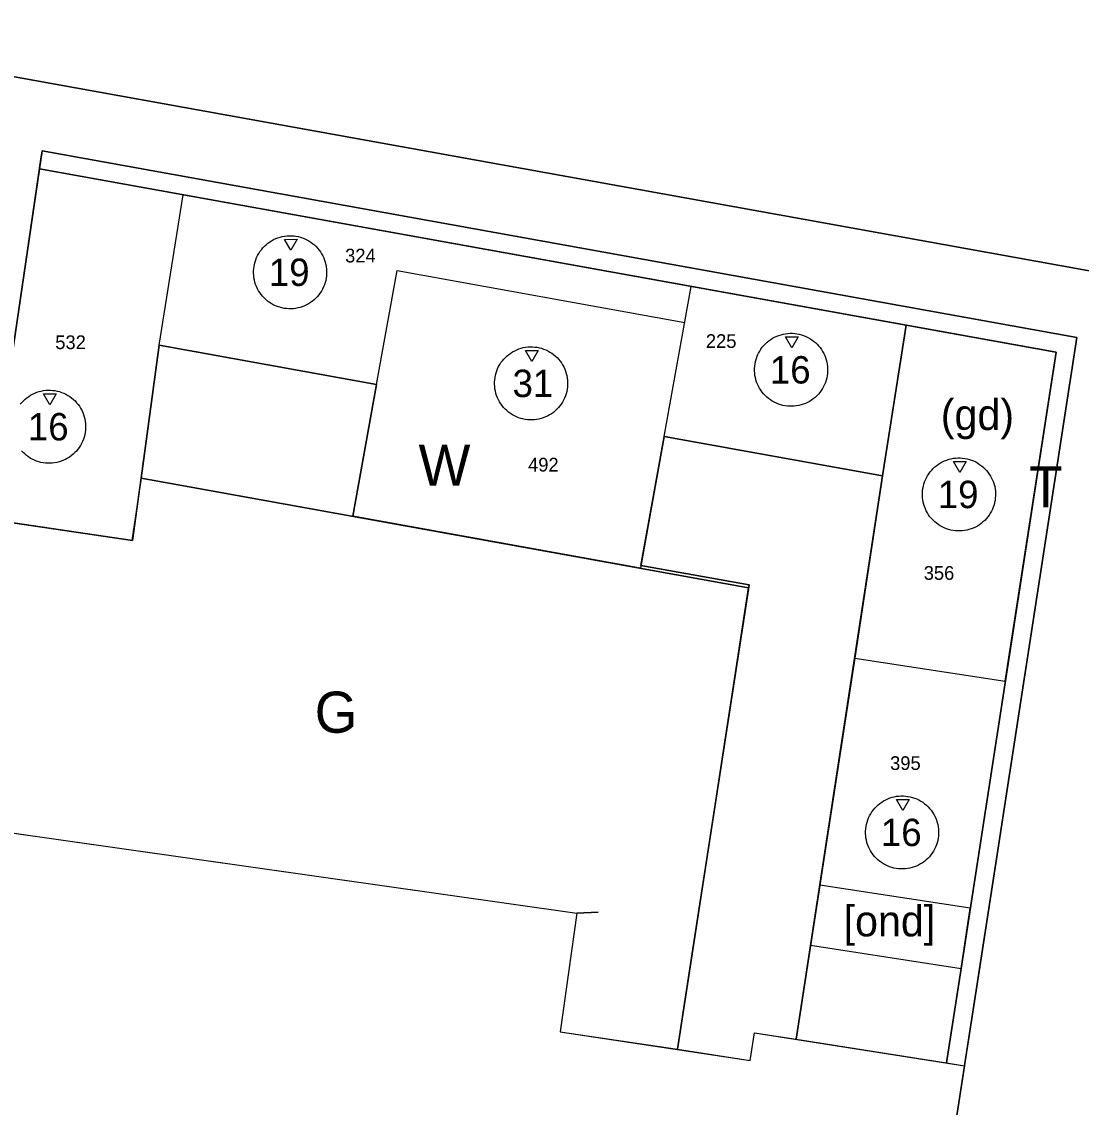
# Model space of a CAD drawing. Extents: x 104705 to 105186, y 424858 to 425816.
# Drawn here: x 104905.1 to 104992.1, y 424996.8 to 425086 of the extents above; entities that cross this region are included whole.
import ezdxf

# ---------------------------------------------------------------- set-up
doc = ezdxf.new("R2010")
doc.units = 0
for name, color, linetype in [('BP_ALG_bestemminggrens', 7, 'Continuous'), ('BP_BA_onderdoorgang', 7, 'Continuous'), ('BP_BPG_Plangebied', 7, 'Continuous'), ('BP_BV_Bouwvlak', 7, 'Continuous'), ('BP_DB_Waarde - Archeologie - 3', 7, 'Continuous'), ('BP_EB_Groen', 7, 'Continuous'), ('BP_EB_Tuin', 7, 'Continuous'), ('BP_EB_Verkeer', 7, 'Continuous'), ('BP_EB_Wonen', 7, 'Continuous'), ('BP_FA_gemengd', 7, 'Continuous'), ('BP_MV_maatvoering', 7, 'Continuous'), ('BP_TXT_tekst', 7, 'Continuous'), ('Default', 7, 'Continuous')]:
    doc.layers.add(name, color=color, linetype=linetype)

msp = doc.modelspace()

# ---------------------------------------------------------------- linework, layer by layer
at = {"layer": 'BP_ALG_bestemminggrens'}
for p, q in [((104904.141, 425057.488), (104906.778, 425075.366)), ((104991.727, 425060.043), (104906.778, 425075.366)), ((104906.559, 425073.882), (104990.022, 425058.827)), ((104984.386, 425012.461), (104991.727, 425060.043)), ((104990.022, 425058.827), (104982.903, 425012.689)), ((104914.903, 425048.497), (104964.78, 425039.501)), ((104982.903, 425012.689), (104982.217, 425008.242)), ((104983.7, 425008.013), (104984.386, 425012.461)), ((104982.217, 425008.242), (104981.021, 425000.489))]:
    msp.add_line(p, q, dxfattribs=at)
for points in [[(104894.145, 425020.819), (104895.344, 425028.689), (104897.865, 425045.778), (104914.194, 425043.37), (104914.903, 425048.497)], [(104964.78, 425039.501), (104958.936, 425001.623)], [(104977.634, 424968.696), (104983.7, 425008.013)]]:
    msp.add_lwpolyline(points, dxfattribs=at)
at = {"layer": 'BP_BA_onderdoorgang'}
msp.add_lwpolyline([(104969.863, 425010.148), (104982.217, 425008.242), (104982.98, 425013.183), (104970.626, 425015.089)], close=True, dxfattribs=at)
at = {"layer": 'BP_BPG_Plangebied'}
for points in [[(104878.613, 425085.968), (104884.922, 425084.964), (104929.095, 425077.019), (104992.295, 425065.592), (105021.483, 425060.269), (105072.728, 425051.043), (105083.131, 425049.138)], [(104884.082, 425017.207), (104884.802, 425022.147), (104950.686, 425012.785), (104949.318, 425003.038)], [(104949.318, 425003.038), (104964.917, 425000.694), (104965.27, 425002.967), (104981.021, 425000.489), (104982.501, 425000.245), (104977.634, 424968.696)]]:
    msp.add_lwpolyline(points, dxfattribs=at)
at = {"layer": 'BP_BV_Bouwvlak'}
for p, q in [((104904.141, 425057.488), (104906.559, 425073.882)), ((104906.559, 425073.882), (104989.997, 425058.831)), ((104916.372, 425059.41), (104914.194, 425043.37)), ((104934.236, 425056.188), (104916.372, 425059.41)), ((104990.022, 425058.827), (104981.021, 425000.489)), ((104932.283, 425045.362), (104934.236, 425056.188)), ((104957.855, 425051.927), (104955.902, 425041.102)), ((104975.785, 425048.693), (104957.855, 425051.927)), ((104975.785, 425048.693), (104957.855, 425051.927)), ((104968.674, 425002.44), (104975.785, 425048.693)), ((104914.194, 425043.37), (104888.499, 425047.16)), ((104955.902, 425041.102), (104932.283, 425045.362))]:
    msp.add_line(p, q, dxfattribs=at)
at = {"layer": 'BP_DB_Waarde - Archeologie - 3'}
for points in [[(105083.131, 425049.138), (105072.728, 425051.043), (105021.483, 425060.269), (104992.295, 425065.592), (104929.095, 425077.019), (104884.922, 425084.964), (104878.613, 425085.968)], [(104884.082, 425017.207), (104884.802, 425022.147), (104950.686, 425012.785), (104952.424, 425012.852), (104950.686, 425012.785), (104949.318, 425003.038), (104964.917, 425000.694), (104965.27, 425002.967), (104982.501, 425000.245)], [(104982.501, 425000.245), (104977.634, 424968.696), (104977.634, 424968.696)]]:
    msp.add_lwpolyline(points, dxfattribs=at)
at = {"layer": 'BP_EB_Groen'}
for p, q in [((104884.802, 425022.147), (104950.686, 425012.785)), ((104950.686, 425012.785), (104949.318, 425003.038)), ((104950.686, 425012.785), (104950.686, 425012.785)), ((104950.686, 425012.785), (104950.686, 425012.785)), ((104950.686, 425012.785), (104950.686, 425012.785))]:
    msp.add_line(p, q, dxfattribs=at)
for points in [[(104961.536, 425018.477), (104964.78, 425039.501), (104914.903, 425048.497), (104914.148, 425043.377), (104897.865, 425045.778), (104895.354, 425028.752), (104894.145, 425020.819), (104884.802, 425022.147), (104885.988, 425030.133)], [(104960.474, 425011.597), (104961.536, 425018.477), (104961.536, 425018.477)], [(104949.318, 425003.038), (104958.936, 425001.623), (104960.474, 425011.597)]]:
    msp.add_lwpolyline(points, dxfattribs=at)
at = {"layer": 'BP_EB_Tuin'}
for points in [[(104982.903, 425012.689), (104981.021, 425000.489), (104982.501, 425000.245), (104984.386, 425012.461), (104991.727, 425060.043), (104906.778, 425075.366), (104906.559, 425073.881)], [(104906.559, 425073.881), (104990.022, 425058.827), (104982.903, 425012.689)]]:
    msp.add_lwpolyline(points, dxfattribs=at)
at = {"layer": 'BP_EB_Verkeer'}
for p, q in [((104984.386, 425012.461), (104983.7, 425008.013)), ((104984.386, 425012.461), (104984.386, 425012.461)), ((104984.386, 425012.461), (104984.386, 425012.461)), ((104983.7, 425008.013), (104977.634, 424968.696))]:
    msp.add_line(p, q, dxfattribs=at)
for points in [[(105083.131, 425049.138), (105072.728, 425051.043), (105021.483, 425060.269), (104992.295, 425065.592), (104929.095, 425077.019), (104884.922, 425084.964), (104878.613, 425085.968)], [(104904.364, 425058.96), (104904.357, 425058.961), (104906.705, 425074.871)], [(104906.705, 425074.871), (104906.778, 425075.366), (104991.727, 425060.043), (104984.386, 425012.461)]]:
    msp.add_lwpolyline(points, dxfattribs=at)
at = {"layer": 'BP_EB_Wonen'}
for p, q in [((104906.559, 425073.882), (104904.141, 425057.488)), ((104990.022, 425058.827), (104906.559, 425073.882)), ((104916.372, 425059.41), (104914.903, 425048.497)), ((104914.903, 425048.497), (104916.372, 425059.41)), ((104934.236, 425056.188), (104916.372, 425059.41)), ((104916.372, 425059.41), (104934.236, 425056.188)), ((104982.903, 425012.689), (104990.022, 425058.827)), ((104932.283, 425045.362), (104934.236, 425056.188)), ((104934.236, 425056.188), (104932.283, 425045.362)), ((104957.855, 425051.927), (104955.943, 425041.327)), ((104955.943, 425041.327), (104957.855, 425051.927)), ((104975.785, 425048.693), (104957.855, 425051.927)), ((104957.855, 425051.927), (104975.785, 425048.693)), ((104914.903, 425048.497), (104932.283, 425045.362)), ((104973.5, 425033.72), (104975.785, 425048.693)), ((104975.785, 425048.693), (104973.5, 425033.72)), ((104932.283, 425045.362), (104964.78, 425039.501)), ((104955.943, 425041.327), (104964.814, 425039.727)), ((104964.814, 425039.727), (104955.943, 425041.327)), ((104964.814, 425039.727), (104960.474, 425011.597)), ((104964.78, 425039.501), (104964.814, 425039.727)), ((104968.674, 425002.44), (104973.5, 425033.72)), ((104973.5, 425033.72), (104968.674, 425002.44)), ((104982.217, 425008.243), (104982.903, 425012.689))]:
    msp.add_line(p, q, dxfattribs=at)
for points in [[(104897.865, 425045.778), (104914.194, 425043.37), (104914.903, 425048.497)], [(104960.474, 425011.597), (104958.936, 425001.623), (104964.917, 425000.694), (104965.27, 425002.967), (104968.674, 425002.44)], [(104968.674, 425002.44), (104981.021, 425000.489), (104982.217, 425008.243)]]:
    msp.add_lwpolyline(points, dxfattribs=at)
at = {"layer": 'BP_FA_gemengd'}
msp.add_lwpolyline([(104975.785, 425048.693), (104973.5, 425033.72), (104985.854, 425031.814), (104990.022, 425058.827), (104977.716, 425061.046)], close=True, dxfattribs=at)
at = {"layer": 'BP_MV_maatvoering'}
for p, q in [((104916.372, 425059.41), (104918.363, 425071.752)), ((104934.236, 425056.188), (104935.922, 425065.537)), ((104935.922, 425065.537), (104959.541, 425061.276)), ((104957.855, 425051.927), (104960.073, 425064.229)), ((104975.785, 425048.693), (104977.716, 425061.046)), ((104973.5, 425033.72), (104985.854, 425031.814))]:
    msp.add_line(p, q, dxfattribs=at)
for points in [[(104929.798, 425064.022), (104929.707, 425063.857), (104929.605, 425063.698), (104929.494, 425063.546), (104929.372, 425063.402), (104929.243, 425063.266), (104929.105, 425063.137), (104928.96, 425063.017), (104928.807, 425062.907), (104928.646, 425062.807), (104928.481, 425062.717), (104928.31, 425062.637), (104928.135, 425062.57), (104927.955, 425062.513), (104927.772, 425062.466), (104927.587, 425062.432), (104927.4, 425062.409), (104927.212, 425062.399), (104927.023, 425062.399), (104926.836, 425062.412), (104926.648, 425062.436), (104926.464, 425062.472), (104926.281, 425062.52), (104926.102, 425062.58), (104925.927, 425062.651), (104925.757, 425062.732), (104925.592, 425062.823), (104925.433, 425062.925), (104925.282, 425063.036), (104925.138, 425063.158), (104925.001, 425063.287), (104924.872, 425063.425), (104924.752, 425063.57), (104924.643, 425063.723), (104924.542, 425063.884), (104924.452, 425064.049), (104924.373, 425064.22), (104924.305, 425064.395), (104924.248, 425064.575), (104924.202, 425064.758), (104924.167, 425064.943), (104924.145, 425065.13), (104924.134, 425065.318), (104924.134, 425065.507), (104924.148, 425065.694), (104924.172, 425065.882), (104924.208, 425066.066), (104924.256, 425066.249), (104924.316, 425066.428), (104924.386, 425066.603), (104924.467, 425066.773), (104924.559, 425066.938), (104924.661, 425067.097), (104924.772, 425067.248), (104924.893, 425067.392), (104925.022, 425067.529), (104925.16, 425067.658), (104925.306, 425067.778), (104925.459, 425067.887), (104925.619, 425067.988), (104925.784, 425068.078), (104925.955, 425068.157), (104926.131, 425068.225), (104926.311, 425068.282), (104926.494, 425068.328), (104926.678, 425068.363), (104926.866, 425068.385), (104927.053, 425068.396), (104927.242, 425068.396), (104927.43, 425068.382), (104927.617, 425068.358), (104927.802, 425068.322), (104927.985, 425068.274), (104928.163, 425068.214), (104928.339, 425068.144), (104928.508, 425068.063), (104928.673, 425067.971), (104928.832, 425067.869), (104928.984, 425067.758), (104929.128, 425067.637), (104929.264, 425067.508), (104929.393, 425067.37), (104929.513, 425067.224), (104929.623, 425067.071), (104929.723, 425066.911), (104929.813, 425066.746), (104929.893, 425066.575), (104929.96, 425066.399), (104930.017, 425066.219), (104930.064, 425066.036), (104930.098, 425065.852), (104930.121, 425065.664), (104930.131, 425065.477), (104930.131, 425065.288), (104930.118, 425065.1), (104930.094, 425064.913), (104930.058, 425064.728), (104930.01, 425064.545), (104929.95, 425064.367), (104929.879, 425064.191)], [(104927.202, 425067.2), (104926.68, 425068.097), (104927.719, 425068.102)], [(104970.931, 425056.014), (104970.839, 425055.849), (104970.737, 425055.69), (104970.626, 425055.538), (104970.505, 425055.394), (104970.376, 425055.258), (104970.238, 425055.129), (104970.092, 425055.009), (104969.939, 425054.899), (104969.779, 425054.799), (104969.614, 425054.709), (104969.443, 425054.629), (104969.267, 425054.562), (104969.087, 425054.505), (104968.904, 425054.458), (104968.72, 425054.424), (104968.532, 425054.401), (104968.345, 425054.391), (104968.156, 425054.391), (104967.968, 425054.404), (104967.781, 425054.428), (104967.596, 425054.464), (104967.413, 425054.512), (104967.235, 425054.572), (104967.059, 425054.643), (104966.89, 425054.724), (104966.725, 425054.815), (104966.566, 425054.917), (104966.414, 425055.028), (104966.27, 425055.15), (104966.134, 425055.279), (104966.005, 425055.417), (104965.885, 425055.562), (104965.775, 425055.715), (104965.675, 425055.876), (104965.585, 425056.041), (104965.505, 425056.212), (104965.438, 425056.387), (104965.381, 425056.567), (104965.334, 425056.75), (104965.3, 425056.935), (104965.277, 425057.122), (104965.267, 425057.31), (104965.267, 425057.499), (104965.28, 425057.686), (104965.304, 425057.874), (104965.34, 425058.058), (104965.388, 425058.241), (104965.448, 425058.42), (104965.519, 425058.595), (104965.6, 425058.765), (104965.691, 425058.93), (104965.793, 425059.089), (104965.904, 425059.24), (104966.026, 425059.384), (104966.155, 425059.521), (104966.293, 425059.65), (104966.438, 425059.77), (104966.591, 425059.879), (104966.752, 425059.98), (104966.917, 425060.07), (104967.088, 425060.149), (104967.263, 425060.217), (104967.443, 425060.274), (104967.626, 425060.32), (104967.811, 425060.355), (104967.998, 425060.377), (104968.186, 425060.388), (104968.375, 425060.388), (104968.562, 425060.374), (104968.75, 425060.35), (104968.934, 425060.314), (104969.117, 425060.266), (104969.296, 425060.206), (104969.471, 425060.136), (104969.641, 425060.055), (104969.806, 425059.963), (104969.965, 425059.861), (104970.116, 425059.75), (104970.26, 425059.629), (104970.397, 425059.5), (104970.526, 425059.362), (104970.646, 425059.216), (104970.755, 425059.063), (104970.856, 425058.903), (104970.946, 425058.738), (104971.025, 425058.567), (104971.093, 425058.391), (104971.15, 425058.211), (104971.196, 425058.028), (104971.231, 425057.844), (104971.253, 425057.656), (104971.264, 425057.469), (104971.264, 425057.28), (104971.25, 425057.092), (104971.226, 425056.905), (104971.19, 425056.72), (104971.142, 425056.537), (104971.082, 425056.359), (104971.012, 425056.183)], [(104968.334, 425059.192), (104967.812, 425060.089), (104968.852, 425060.094)], [(104949.586, 425054.902), (104949.495, 425054.737), (104949.393, 425054.578), (104949.282, 425054.426), (104949.16, 425054.282), (104949.031, 425054.146), (104948.893, 425054.017), (104948.748, 425053.897), (104948.595, 425053.787), (104948.434, 425053.687), (104948.269, 425053.597), (104948.098, 425053.517), (104947.923, 425053.45), (104947.743, 425053.393), (104947.56, 425053.346), (104947.375, 425053.312), (104947.188, 425053.289), (104947, 425053.279), (104946.811, 425053.279), (104946.624, 425053.292), (104946.436, 425053.316), (104946.252, 425053.352), (104946.069, 425053.4), (104945.89, 425053.46), (104945.715, 425053.531), (104945.545, 425053.612), (104945.38, 425053.703), (104945.221, 425053.805), (104945.07, 425053.916), (104944.926, 425054.038), (104944.789, 425054.167), (104944.66, 425054.305), (104944.54, 425054.45), (104944.431, 425054.603), (104944.33, 425054.764), (104944.24, 425054.929), (104944.161, 425055.1), (104944.093, 425055.275), (104944.036, 425055.455), (104943.99, 425055.638), (104943.955, 425055.823), (104943.933, 425056.01), (104943.922, 425056.198), (104943.922, 425056.387), (104943.936, 425056.574), (104943.96, 425056.762), (104943.996, 425056.946), (104944.044, 425057.129), (104944.104, 425057.308), (104944.174, 425057.483), (104944.255, 425057.653), (104944.347, 425057.818), (104944.449, 425057.977), (104944.56, 425058.128), (104944.681, 425058.272), (104944.81, 425058.409), (104944.948, 425058.538), (104945.094, 425058.658), (104945.247, 425058.767), (104945.407, 425058.868), (104945.572, 425058.958), (104945.743, 425059.037), (104945.919, 425059.105), (104946.099, 425059.162), (104946.282, 425059.208), (104946.466, 425059.243), (104946.654, 425059.265), (104946.841, 425059.276), (104947.03, 425059.276), (104947.218, 425059.262), (104947.405, 425059.238), (104947.59, 425059.202), (104947.773, 425059.154), (104947.951, 425059.094), (104948.127, 425059.024), (104948.296, 425058.943), (104948.461, 425058.851), (104948.62, 425058.749), (104948.772, 425058.638), (104948.916, 425058.517), (104949.052, 425058.388), (104949.181, 425058.25), (104949.301, 425058.104), (104949.411, 425057.951), (104949.511, 425057.791), (104949.601, 425057.626), (104949.681, 425057.455), (104949.748, 425057.279), (104949.805, 425057.099), (104949.852, 425056.916), (104949.886, 425056.732), (104949.909, 425056.544), (104949.919, 425056.357), (104949.919, 425056.168), (104949.906, 425055.98), (104949.882, 425055.793), (104949.846, 425055.608), (104949.798, 425055.425), (104949.738, 425055.247), (104949.667, 425055.071)], [(104946.99, 425058.08), (104946.468, 425058.977), (104947.507, 425058.982)], [(104907.414, 425054.521), (104906.892, 425055.418), (104907.931, 425055.423)], [(104984.715, 425045.781), (104984.624, 425045.616), (104984.522, 425045.457), (104984.411, 425045.306), (104984.289, 425045.162), (104984.16, 425045.025), (104984.022, 425044.896), (104983.877, 425044.776), (104983.724, 425044.667), (104983.563, 425044.566), (104983.398, 425044.476), (104983.227, 425044.397), (104983.052, 425044.329), (104982.872, 425044.272), (104982.689, 425044.226), (104982.504, 425044.191), (104982.317, 425044.169), (104982.129, 425044.158), (104981.94, 425044.158), (104981.753, 425044.172), (104981.565, 425044.196), (104981.381, 425044.232), (104981.198, 425044.28), (104981.019, 425044.34), (104980.844, 425044.41), (104980.674, 425044.491), (104980.509, 425044.583), (104980.35, 425044.685), (104980.199, 425044.796), (104980.055, 425044.917), (104979.918, 425045.046), (104979.789, 425045.184), (104979.669, 425045.33), (104979.56, 425045.483), (104979.459, 425045.643), (104979.369, 425045.808), (104979.29, 425045.979), (104979.222, 425046.155), (104979.165, 425046.335), (104979.119, 425046.518), (104979.084, 425046.702), (104979.062, 425046.89), (104979.051, 425047.077), (104979.051, 425047.266), (104979.065, 425047.454), (104979.089, 425047.641), (104979.125, 425047.826), (104979.173, 425048.009), (104979.233, 425048.187), (104979.303, 425048.363), (104979.384, 425048.532), (104979.476, 425048.697), (104979.578, 425048.856), (104979.689, 425049.008), (104979.81, 425049.152), (104979.939, 425049.288), (104980.077, 425049.417), (104980.223, 425049.537), (104980.376, 425049.647), (104980.536, 425049.747), (104980.701, 425049.837), (104980.872, 425049.917), (104981.048, 425049.984), (104981.228, 425050.041), (104981.411, 425050.088), (104981.595, 425050.122), (104981.783, 425050.145), (104981.97, 425050.155), (104982.159, 425050.155), (104982.347, 425050.142), (104982.534, 425050.118), (104982.719, 425050.082), (104982.902, 425050.034), (104983.08, 425049.974), (104983.256, 425049.903), (104983.425, 425049.822), (104983.59, 425049.731), (104983.749, 425049.629), (104983.901, 425049.518), (104984.045, 425049.396), (104984.181, 425049.267), (104984.31, 425049.129), (104984.43, 425048.984), (104984.54, 425048.831), (104984.64, 425048.67), (104984.73, 425048.505), (104984.81, 425048.334), (104984.877, 425048.159), (104984.934, 425047.979), (104984.981, 425047.796), (104985.015, 425047.611), (104985.038, 425047.424), (104985.048, 425047.236), (104985.048, 425047.047), (104985.035, 425046.86), (104985.011, 425046.672), (104984.975, 425046.488), (104984.927, 425046.305), (104984.867, 425046.126), (104984.796, 425045.951)], [(104982.119, 425048.96), (104981.597, 425049.857), (104982.636, 425049.861)], [(104980.046, 425018.033), (104979.955, 425017.868), (104979.853, 425017.709), (104979.742, 425017.558), (104979.62, 425017.414), (104979.491, 425017.277), (104979.353, 425017.148), (104979.208, 425017.028), (104979.055, 425016.919), (104978.894, 425016.818), (104978.729, 425016.728), (104978.558, 425016.649), (104978.383, 425016.581), (104978.203, 425016.524), (104978.02, 425016.478), (104977.835, 425016.443), (104977.648, 425016.421), (104977.46, 425016.41), (104977.271, 425016.41), (104977.084, 425016.424), (104976.896, 425016.448), (104976.712, 425016.484), (104976.529, 425016.532), (104976.35, 425016.592), (104976.175, 425016.662), (104976.005, 425016.743), (104975.84, 425016.835), (104975.681, 425016.937), (104975.53, 425017.048), (104975.386, 425017.169), (104975.249, 425017.298), (104975.12, 425017.436), (104975, 425017.582), (104974.891, 425017.735), (104974.79, 425017.895), (104974.7, 425018.06), (104974.621, 425018.231), (104974.553, 425018.407), (104974.496, 425018.587), (104974.45, 425018.77), (104974.415, 425018.954), (104974.393, 425019.142), (104974.382, 425019.329), (104974.382, 425019.518), (104974.396, 425019.706), (104974.42, 425019.893), (104974.456, 425020.078), (104974.504, 425020.261), (104974.564, 425020.439), (104974.634, 425020.615), (104974.715, 425020.784), (104974.807, 425020.949), (104974.909, 425021.108), (104975.02, 425021.26), (104975.141, 425021.404), (104975.27, 425021.54), (104975.408, 425021.669), (104975.554, 425021.789), (104975.707, 425021.899), (104975.867, 425021.999), (104976.032, 425022.089), (104976.203, 425022.169), (104976.379, 425022.236), (104976.559, 425022.293), (104976.742, 425022.34), (104976.926, 425022.374), (104977.114, 425022.397), (104977.301, 425022.407), (104977.49, 425022.407), (104977.678, 425022.394), (104977.865, 425022.37), (104978.05, 425022.334), (104978.233, 425022.286), (104978.411, 425022.226), (104978.587, 425022.155), (104978.756, 425022.074), (104978.921, 425021.983), (104979.08, 425021.881), (104979.232, 425021.77), (104979.376, 425021.648), (104979.512, 425021.519), (104979.641, 425021.381), (104979.761, 425021.236), (104979.871, 425021.083), (104979.971, 425020.922), (104980.061, 425020.757), (104980.141, 425020.586), (104980.208, 425020.411), (104980.265, 425020.231), (104980.312, 425020.048), (104980.346, 425019.863), (104980.369, 425019.676), (104980.379, 425019.488), (104980.379, 425019.299), (104980.366, 425019.112), (104980.342, 425018.924), (104980.306, 425018.74), (104980.258, 425018.557), (104980.198, 425018.378), (104980.127, 425018.203)], [(104977.45, 425021.212), (104976.928, 425022.109), (104977.967, 425022.113)]]:
    msp.add_lwpolyline(points, close=True, dxfattribs=at)
msp.add_lwpolyline([(104904.984, 425054.569), (104905.105, 425054.713), (104905.234, 425054.85), (104905.372, 425054.979), (104905.518, 425055.099), (104905.671, 425055.208), (104905.831, 425055.309), (104905.996, 425055.399), (104906.167, 425055.478), (104906.343, 425055.546), (104906.523, 425055.603), (104906.706, 425055.649), (104906.89, 425055.684), (104907.078, 425055.706), (104907.265, 425055.717), (104907.454, 425055.717), (104907.642, 425055.703), (104907.829, 425055.679), (104908.014, 425055.643), (104908.197, 425055.595), (104908.375, 425055.535), (104908.551, 425055.465), (104908.72, 425055.384), (104908.885, 425055.292), (104909.044, 425055.19), (104909.196, 425055.079), (104909.34, 425054.958), (104909.476, 425054.829), (104909.605, 425054.691), (104909.725, 425054.545), (104909.835, 425054.392), (104909.935, 425054.232), (104910.025, 425054.067), (104910.105, 425053.896), (104910.172, 425053.72), (104910.229, 425053.54), (104910.276, 425053.357), (104910.31, 425053.173), (104910.333, 425052.985), (104910.343, 425052.798), (104910.343, 425052.609), (104910.33, 425052.421), (104910.306, 425052.234), (104910.27, 425052.049), (104910.222, 425051.866), (104910.162, 425051.688), (104910.091, 425051.512), (104910.01, 425051.343), (104909.919, 425051.178), (104909.817, 425051.019), (104909.706, 425050.867), (104909.584, 425050.723), (104909.455, 425050.587), (104909.317, 425050.458), (104909.172, 425050.338), (104909.019, 425050.228), (104908.858, 425050.128), (104908.693, 425050.038), (104908.522, 425049.958), (104908.347, 425049.891), (104908.167, 425049.834), (104907.984, 425049.787), (104907.799, 425049.753), (104907.612, 425049.73), (104907.424, 425049.72), (104907.235, 425049.72), (104907.048, 425049.733), (104906.86, 425049.757), (104906.676, 425049.793), (104906.493, 425049.841), (104906.314, 425049.901), (104906.139, 425049.972), (104905.969, 425050.053), (104905.804, 425050.144), (104905.645, 425050.246), (104905.494, 425050.357), (104905.35, 425050.479), (104905.213, 425050.608), (104905.084, 425050.746)], dxfattribs=at)

# ---------------------------------------------------------------- texts
for s, p in [('19', (104925.388, 425064.272)), ('16', (104966.522, 425056.264)), ('31', (104945.395, 425055.152)), ('16', (104905.602, 425051.593)), ('19', (104980.305, 425046.032)), ('16', (104975.638, 425018.284))]:
    msp.add_text(s, height=2.25, dxfattribs=at).set_placement(p)
at = {"layer": 'BP_TXT_tekst'}
for s, height, p in [('(gd)', 2.5312, (104980.556, 425052.445)), ('W', 3.375, (104937.678, 425047.871)), ('T', 3.375, (104987.806, 425046.098)), ('G', 3.375, (104929.152, 425027.594)), ('[ond]', 2.5312, (104972.578, 425010.874))]:
    msp.add_text(s, height=height, dxfattribs=at).set_placement(p)
at = {"layer": 'Default'}
for s, p in [('324', (104931.651, 425066.202)), ('532', (104907.854, 425059.087)), ('225', (104961.27, 425059.186)), ('492', (104946.672, 425049.04)), ('356', (104979.157, 425040.146)), ('395', (104976.396, 425024.537))]:
    msp.add_text(s, height=1.125, dxfattribs=at).set_placement(p)

doc.saveas('drawing.dxf')
